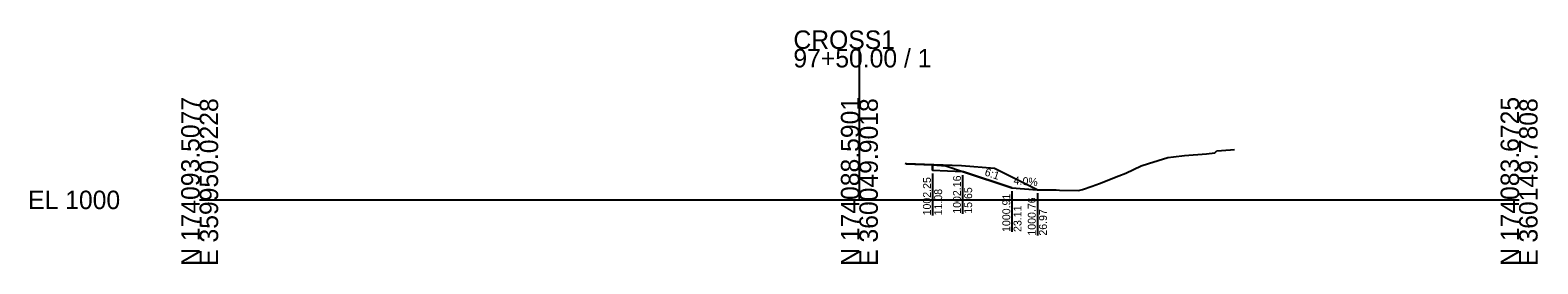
# Model space of a CAD drawing. Extents: x -26 to 1403, y -10 to 11027.
# Drawn here: x 1174.3 to 1402.8, y 990.3 to 1025.7 of the extents above; entities that cross this region are included whole.
import ezdxf

# ---------------------------------------------------------------- set-up
doc = ezdxf.new("R2010")
doc.units = 0
for name, color, linetype in [('Default', 7, 'Continuous'), ('P_E_XS_Ground', 7, 'Continuous'), ('P_XS', 7, 'Continuous'), ('P_XS_EAR_CommonGrnd', 7, 'Continuous'), ('P_XS_Lane', 7, 'Continuous'), ('P_XS_Rock', 7, 'Continuous')]:
    doc.layers.add(name, color=color, linetype=linetype)

msp = doc.modelspace()

# ---------------------------------------------------------------- linework, layer by layer
at = {"layer": 'Default'}
for p, q in [((1300, 1000), (1300, 1022.88)), ((1200, 1000), (1300, 1000)), ((1300, 1000), (1400, 1000))]:
    msp.add_line(p, q, dxfattribs=at)
at = {"layer": 'P_E_XS_Ground'}
for p, q in [((1342.71, 1005.14), (1343.81, 1005.54)), ((1343.81, 1005.54), (1346.73, 1006.43)), ((1346.73, 1006.43), (1347.6, 1006.52)), ((1347.6, 1006.52), (1349.3, 1006.72)), ((1349.3, 1006.72), (1352.59, 1006.99)), ((1352.59, 1006.99), (1353.9, 1007.14)), ((1353.9, 1007.14), (1354.18, 1007.46)), ((1354.18, 1007.46), (1356.23, 1007.59)), ((1356.23, 1007.59), (1356.86, 1007.63)), ((1307.08, 1005.49), (1306.96, 1005.5)), ((1315.5, 1005.15), (1307.08, 1005.49)), ((1320.5, 1004.75), (1315.5, 1005.15)), ((1326.97, 1001.52), (1320.5, 1004.75)), ((1336.42, 1002.5), (1339.31, 1003.63)), ((1339.31, 1003.63), (1340.41, 1004.05)), ((1340.41, 1004.05), (1342.71, 1005.14)), ((1326.97, 1001.52), (1329.1, 1001.5)), ((1329.1, 1001.5), (1329.81, 1001.52)), ((1329.81, 1001.52), (1330.31, 1001.49)), ((1330.31, 1001.49), (1333.19, 1001.44)), ((1333.19, 1001.44), (1333.8, 1001.57)), ((1333.8, 1001.57), (1335.3, 1002.09)), ((1335.3, 1002.09), (1336.42, 1002.5))]:
    msp.add_line(p, q, dxfattribs=at)
at = {"layer": 'P_XS'}
for p, q in [((1307.08, 1005.49), (1311.08, 1005.33)), ((1311.08, 1005.33), (1313.08, 1005.17)), ((1313.08, 1005.17), (1315.65, 1004.31))]:
    msp.add_line(p, q, dxfattribs=at)
at = {"layer": 'P_XS_EAR_CommonGrnd'}
msp.add_lwpolyline([(1315.5, 1005.15), (1311.08, 1005.33), (1311.08, 1004.5), (1315.65, 1004.31), (1323.11, 1001.83), (1326.97, 1001.52), (1320.5, 1004.75)], close=True, dxfattribs=at)
at = {"layer": 'P_XS_Lane'}
for p, q in [((1311.08, 1004.5), (1311.08, 1005.33)), ((1311.08, 1004.5), (1315.65, 1004.31)), ((1323.11, 1001.83), (1315.65, 1004.31)), ((1323.11, 1001.83), (1326.97, 1001.52))]:
    msp.add_line(p, q, dxfattribs=at)
at = {"layer": 'P_XS_Rock'}
for p, q in [((1311.09, 1004), (1311.09, 997.65)), ((1315.64, 1003.76), (1315.64, 997.9)), ((1323.12, 1001.3), (1323.12, 995.14)), ((1326.98, 1001.02), (1326.98, 994.58))]:
    msp.add_line(p, q, dxfattribs=at)

# ---------------------------------------------------------------- texts
at = {"layer": 'Default'}
for s, p in [('CROSS1', (1290, 1022.88)), ('97+50.00 / 1', (1290, 1020.08)), ('EL 1000', (1174, 998.6))]:
    msp.add_text(s, height=2.8, dxfattribs=at).set_placement(p)
for s, p in [('N 174093.5077', (1200, 990)), ('E 359950.0228', (1202.8, 990)), ('N 174088.5901', (1300, 990)), ('E 360049.9018', (1302.8, 990)), ('N 174083.6725', (1400, 990)), ('E 360149.7808', (1402.8, 990))]:
    msp.add_text(s, height=2.8, rotation=90, dxfattribs=at).set_placement(p)
at = {"layer": 'P_XS_Rock'}
for s, rotation, p in [('1002.25', 90, (1310.84, 997.65)), ('1002.16', 90, (1315.39, 997.9)), ('6:1', 341.5651, (1318.89, 1003.73)), ('4.0%', 355.4261, (1323.34, 1002.38)), ('11.08', 90, (1312.54, 997.65)), ('15.65', 90, (1317.09, 997.9)), ('1000.91', 90, (1322.87, 995.14)), ('23.11', 90, (1324.57, 995.14)), ('1000.76', 90, (1326.73, 994.58)), ('26.97', 90, (1328.43, 994.58))]:
    msp.add_text(s, height=1.2, rotation=rotation, dxfattribs=at).set_placement(p)

doc.saveas('drawing.dxf')
